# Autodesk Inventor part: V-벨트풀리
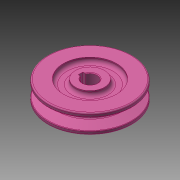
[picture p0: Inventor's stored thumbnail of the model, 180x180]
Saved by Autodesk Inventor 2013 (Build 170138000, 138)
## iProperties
Created: 2015-12
Part Number: V-벨트풀리
Material: 강철, 연강
Document SubType Name: Modeling
Designer: mdu
Density: 7.86 g/cm^3
CustomPartVersion: 1
Author: mdu
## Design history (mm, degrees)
sketch "주 스케치"
  geometry: L1 (0, 16)-(34.7, 16); L2 (34.7, 16)-(34.7, 12.825); L3 (34.7, 12.825)-(25.7, 10.074); L4 (25.7, 10.074)-(25.7, 5.926); L5 (25.7, 5.926)-(34.7, 3.175); L6 (34.7, 3.175)-(34.7, 0); L7 (34.7, 0)-(0, 0); L8 (32, 12)-(32, 4); L9 (25.7, 8)-(32, 8); L10 (34.7, 12.825)-(34.7, 3.175); L11 (0, -3.2)-(0, 19.2) reference; L12 (0, 0)-(0, 16)
  constraints: 22 end point, 5 perpendicular, 2 collinear, 2 midpoint, 2 point on line, 1 parallel
  dimensions: "d0" = 8 distance of L8.start L8.end (= da_Bw); "d1" = 34 deg angle of L3 L5 (= da_Alfa); "d2" = 2.7 distance between parallel lines of L2 L8 (= da_c); "d6" = 16 distance between parallel lines of L7 L1 (computed from d5, da_ng, da_Sg); "d21" = 64 diameter of L8 L11 (= da_Dw); "d25" = 9 distance between parallel lines of L4 L10 (= da_Hd); "d27" = 8 distance between parallel lines of L7 L9 (= da_Se)
node "벨트 평면"
revolve "본체" stored, may be unused: angle "d7" = 90 deg
revolve "그루브" stored, may be unused: angle "d15" = 90 deg
feature "허브 키홈"
fillet "모깎기3" dims "d28" = 0.5, "d29" = 1, "d30" = 1
sketch "스케치2"
  geometry: C1 r 12 at (0, 0); C2 r 22 at (0, 0); 1 further point
  constraints: 2 centre point, 2 coincident
  dimensions: "d31" = 24 diameter of C1; "d32" = 44 diameter of C2
extrude "돌출1" cut sketch "스케치2" distance "d33" = 4; taper "d34" = 0 deg
fillet "모깎기4" dims "d35" = 3
node "작업 평면2"
chamfer "모따기1" distance "d36" = 0.5; stored, may be unused: second distance "d37" = 2, angle "d38" = 45 deg
body "Solid1"
pattern_linear "그루브 패턴" dims "d18" = 12 (= da_Sg)
mirror "대칭1"
other parameters: "d5" = 8 (= da_Se), "da_Bw" = 8 [user parameter; used in 1 equation term], "da_Alfa" = 34 deg [user parameter; used in 1 equation term], "da_c" = 2.7 [user parameter; used in 1 equation term], "da_Dw" = 64 [user parameter; used in 1 equation term], "da_Hd" = 9 (computed from d2) [user parameter; used in 1 equation term], "da_Se" = 8 [user parameter; used in 2 equation terms], "da_Sg" = 12 [user parameter; used in 2 equation terms], "da_r1" = 0 [user parameter], "da_r2" = 0 [user parameter], "d24" = 0, "d26" = 0
